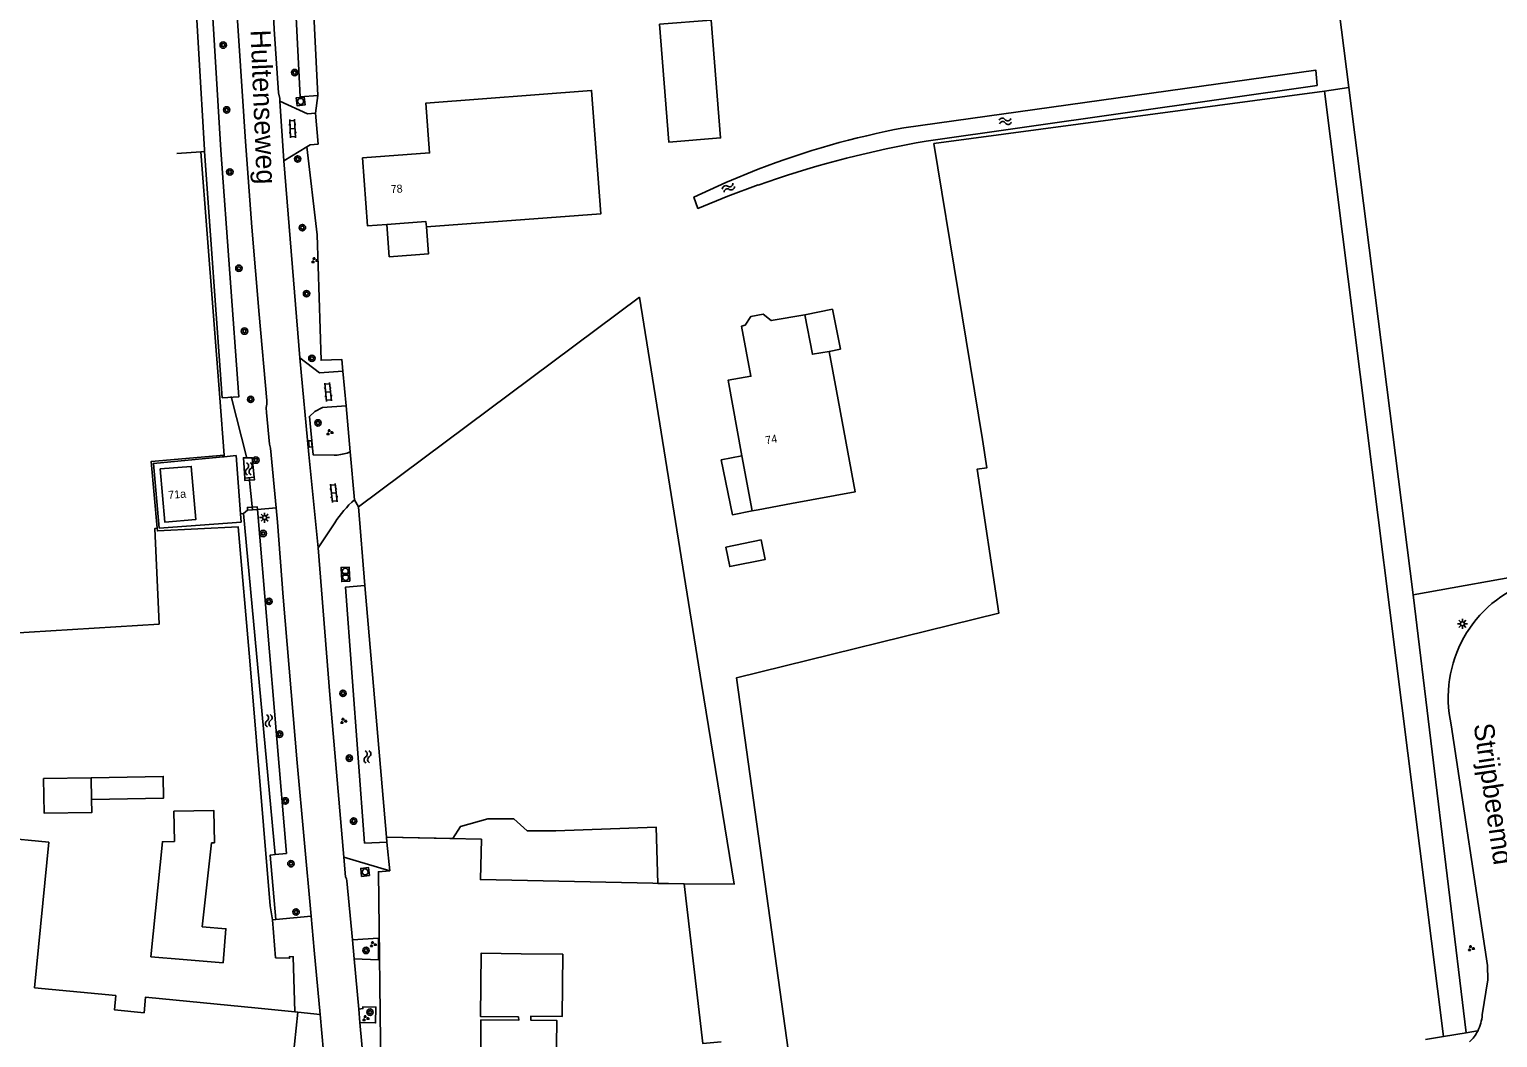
# Model space of a CAD drawing. Extents: x 124000 to 129000, y 395500 to 397503.
# Drawn here: x 125908.9 to 126092.4, y 397257.8 to 397383.8 of the extents above; entities that cross this region are included whole.
import ezdxf

# ---------------------------------------------------------------- set-up
doc = ezdxf.new("R2010")
doc.units = 0
for name, color, linetype in [('gg-afsc-draadraster', 7, 'Continuous'), ('gg-afsc-hekwerk', 7, 'Continuous'), ('gg-afsc-lijn draadraster', 7, 'Continuous'), ('gg-anno-huisnummerreeks BGT', 7, 'Continuous'), ('gg-anno-openbare ruimte label', 7, 'Continuous'), ('gg-bbg-bijgebouw', 7, 'Continuous'), ('gg-bbg-gedigitaliseerde bebouwing', 7, 'Continuous'), ('gg-bbg-gedigitaliseerde bijgebouw', 7, 'Continuous'), ('gg-bbg-hoofdgebouw', 7, 'Continuous'), ('gg-bbg-luifel en loopbrug', 7, 'Continuous'), ('gg-knt-bronhoudergrens', 7, 'Continuous'), ('gg-knt-verharding', 7, 'Continuous'), ('gg-kntw-bovenkant insteek waterloop', 7, 'Continuous'), ('gg-kwrk-duiker nz buis', 7, 'Continuous'), ('gg-kwrk-uitstroombak niveau min 01', 7, 'Continuous'), ('gt-grn-groengrens', 7, 'Continuous'), ('gt-grn-weggrens', 7, 'Continuous'), ('gt-symb-boom', 7, 'Continuous'), ('gt-symb-groenvak', 7, 'Continuous'), ('gt-symb-klinker verharding', 7, 'Continuous'), ('gt-symb-kolk', 7, 'Continuous'), ('gt-symb-lichtmast', 7, 'Continuous'), ('gt-symb-rioolschacht', 7, 'Continuous'), ('gt-symb-watersymbool', 7, 'Continuous'), ('gx-grn-maaiveld', 7, 'Continuous')]:
    doc.layers.add(name, color=color, linetype=linetype)

# ---------------------------------------------------------------- blocks, each defined once
blk = doc.blocks.new('gt0-BOOM')
at = {"layer": 'gt-symb-boom'}
for radius in [0.4, 0.2]:
    blk.add_circle((0, 0), radius, dxfattribs=at)
blk = doc.blocks.new('gt0-LMAST')
at = {"layer": 'gt-symb-lichtmast'}
for p, q in [((-0.18, 0.17), (-0.45, 0.44)), ((-0.01, 0.25), (-0.01, 0.62)), ((0.17, 0.17), (0.44, 0.44)), ((-0.26, 0), (-0.63, 0)), ((-0.18, -0.18), (-0.45, -0.45)), ((-0.01, -0.25), (-0.01, -0.63)), ((0.44, -0.45), (0.17, -0.18)), ((0.24, 0), (0.62, 0))]:
    blk.add_line(p, q, dxfattribs=at)
blk.add_circle((-0.01, 0), 0.25, dxfattribs=at)
blk = doc.blocks.new('gt0-GRVAK')
at = {"layer": 'gt-symb-groenvak'}
for p, q in [((-0.11, 0.19), (-0.23, 0.24)), ((-0.18, 0.15), (0.09, 0.15)), ((-0.09, 0.21), (-0.16, 0.32)), ((-0.05, 0.21), (-0.05, 0.39)), ((0, 0.21), (0.06, 0.32)), ((0.01, 0.19), (0.13, 0.24)), ((0.26, -0.05), (0.2, 0.06)), ((0.3, -0.05), (0.3, 0.13)), ((0.35, -0.05), (0.41, 0.06)), ((-0.25, -0.23), (-0.36, -0.18)), ((-0.32, -0.26), (-0.05, -0.26)), ((-0.23, -0.21), (-0.29, -0.09)), ((-0.18, -0.2), (-0.18, -0.02)), ((-0.14, -0.21), (-0.07, -0.09)), ((-0.12, -0.23), (0, -0.18)), ((0.24, -0.07), (0.12, -0.02)), ((0.17, -0.11), (0.44, -0.11)), ((0.37, -0.07), (0.49, -0.02))]:
    blk.add_line(p, q, dxfattribs=at)
blk = doc.blocks.new('gt0-WA')
at = {"layer": 'gt-symb-watersymbool'}
for centre, start, end in [((-0.32, 0.02), 28.0725, 151.9275), ((0.43, 0.42), 208.0725, 331.9275), ((-0.32, -0.43), 28.0725, 151.9275), ((0.43, -0.03), 208.0725, 331.9275)]:
    blk.add_arc(centre, 0.425, start, end, dxfattribs=at)
blk = doc.blocks.new('gt0-RS')
at = {"layer": 'gt-symb-rioolschacht'}
blk.add_lwpolyline([(-0.5, -0.5), (0.5, -0.5), (0.5, 0.5), (-0.5, 0.5)], close=True, dxfattribs=at)
blk.add_circle((0, 0), 0.375, dxfattribs=at)
blk = doc.blocks.new('gt0-KL1')
at = {"layer": 'gt-symb-klinker verharding'}
for p, q in [((-1.15, 0.3), (1.15, 0.3)), ((-1, -0.3), (-1, 0.3)), ((-0.5, 0.3), (-0.5, 0.45)), ((0, -0.3), (0, 0.3)), ((0.5, 0.3), (0.5, 0.45)), ((1, -0.3), (1, 0.3)), ((-1.15, -0.3), (1.15, -0.3)), ((-0.5, -0.45), (-0.5, -0.3)), ((0.5, -0.45), (0.5, -0.3))]:
    blk.add_line(p, q, dxfattribs=at)
blk = doc.blocks.new('gt0-KOLK')
at = {"layer": 'gt-symb-kolk'}
blk.add_lwpolyline([(0, 0), (0.38, 0), (0.38, 0.4), (-0.38, 0.4), (-0.38, 0), (0, 0)], dxfattribs=at)

msp = doc.modelspace()

# ---------------------------------------------------------------- linework, layer by layer
at = {"layer": 'gg-afsc-draadraster'}
for p, q in [((125985.18, 397350.34), (125950.04, 397324.15)), ((125950.04, 397324.15), (125950.86, 397314.34))]:
    msp.add_line(p, q, dxfattribs=at)
msp.add_lwpolyline([(125924.91, 397321.48), (125924.63, 397321.46), (125925.14, 397309.52), (125900.76, 397308.02)], dxfattribs=at)
at = {"layer": 'gg-afsc-hekwerk'}
for p, q in [((125927.38, 397368.31), (125930.37, 397368.54)), ((125930.37, 397368.54), (125932.72, 397337.77)), ((125932.72, 397337.77), (125933.27, 397330.6)), ((125933.02, 397330.39), (125932.7, 397330.36)), ((125933.29, 397330.42), (125933.02, 397330.39)), ((125934.77, 397330.56), (125933.29, 397330.42)), ((125935.32, 397323.3), (125934.77, 397330.56)), ((125925.16, 397321.49), (125935.4, 397322.26)), ((125935.4, 397322.26), (125935.32, 397323.3)), ((125953.96, 397278.68), (125953.6, 397282.27)), ((125953.96, 397278.68), (125953.6, 397282.27))]:
    msp.add_line(p, q, dxfattribs=at)
for points in [[(125933.27, 397330.6), (125924.16, 397329.84), (125924.91, 397321.48)], [(125932.7, 397330.36), (125924.44, 397329.58), (125925.16, 397321.49)], [(125924.91, 397321.48), (125924.94, 397321.15), (125935.02, 397321.67), (125936.49, 397304.91), (125939.03, 397274.29), (125939.3, 397272.55)], [(125953.96, 397278.68), (125952.55, 397278.56), (125952.87, 397253.92)], [(125953.96, 397278.68), (125952.55, 397278.56), (125952.87, 397253.92)], [(125939.3, 397272.55), (125939.71, 397267.82), (125941.46, 397267.75), (125941.44, 397267.96), (125941.9, 397267.95), (125942.09, 397261.06)]]:
    msp.add_lwpolyline(points, dxfattribs=at)
at = {"layer": 'gg-afsc-lijn draadraster'}
for p, q in [((125985.18, 397350.34), (125950.04, 397324.15)), ((125950.04, 397324.15), (125950.86, 397314.34))]:
    msp.add_line(p, q, dxfattribs=at)
msp.add_lwpolyline([(125995.36, 397257.33), (125993.07, 397257.12), (125990.73, 397277.04), (125965.3, 397277.59), (125965.41, 397282.63), (125953.55, 397282.88)], dxfattribs=at)
at = {"layer": 'gg-bbg-bijgebouw'}
for points in [[(125987.67, 397384.48), (125994.14, 397384.99), (125995.3, 397370.25), (125988.82, 397369.74), (125987.67, 397384.48)], [(125926.99, 397286.12), (125927.06, 397282.35), (125925.57, 397282.32), (125924.13, 397267.94), (125928.16, 397267.61)], [(125926.99, 397286.12), (125931.99, 397286.21), (125932.06, 397282.19), (125931.7, 397282.16), (125930.54, 397271.7), (125933.49, 397271.45), (125933.14, 397267.2), (125928.16, 397267.61)], [(125970.37, 397268.33), (125965.37, 397268.38), (125965.29, 397260.49), (125970.07, 397260.44)], [(125974.76, 397253.7), (125974.83, 397260), (125971.59, 397260.03), (125971.59, 397260.51), (125975.49, 397260.47), (125975.57, 397268.27), (125970.37, 397268.33)], [(125965.36, 397260.05), (125965.33, 397254.73), (125965.47, 397253.72), (125968.56, 397253.72)], [(125965.36, 397260.05), (125970.11, 397260.03), (125970.07, 397260.44)]]:
    msp.add_lwpolyline(points, dxfattribs=at)
at = {"layer": 'gg-bbg-gedigitaliseerde bebouwing'}
for p, q in [((125905.32, 397282.85), (125911.38, 397282.26)), ((125942.49, 397261.02), (125942.09, 397261.06))]:
    msp.add_line(p, q, dxfattribs=at)
msp.add_lwpolyline([(125942.09, 397261.06), (125937.52, 397261.54), (125923.47, 397262.91), (125923.28, 397260.96), (125919.56, 397261.33), (125919.73, 397263.09), (125909.6, 397264.08), (125911.38, 397282.26)], dxfattribs=at)
at = {"layer": 'gg-bbg-gedigitaliseerde bijgebouw'}
for p, q in [((125916.66, 397290.3), (125910.71, 397290.2)), ((125916.71, 397287.6), (125916.66, 397290.3))]:
    msp.add_line(p, q, dxfattribs=at)
for points in [[(125995.95, 397319.14), (126000.36, 397320.03), (126000.85, 397317.58), (125996.44, 397316.69), (125995.95, 397319.14)], [(125910.71, 397290.2), (125910.79, 397285.87), (125916.73, 397285.97), (125916.71, 397287.6)]]:
    msp.add_lwpolyline(points, dxfattribs=at)
at = {"layer": 'gg-bbg-hoofdgebouw'}
for p, q in [((126008.88, 397343.59), (126009.79, 397338.65)), ((125999.23, 397323.66), (125997.96, 397330.55)), ((126000, 397323.8), (125999.23, 397323.66)), ((126000, 397323.8), (126004.14, 397324.56))]:
    msp.add_line(p, q, dxfattribs=at)
for points in [[(125958.55, 397359.16), (125980.33, 397360.77), (125979.19, 397376.2), (125958.49, 397374.62), (125958.95, 397368.38), (125950.57, 397367.76), (125951.19, 397359.26), (125953.61, 397359.44)], [(125953.61, 397359.44), (125958.48, 397359.8), (125958.55, 397359.16)], [(125997.93, 397346.74), (125998.36, 397346.86), (125999.07, 397347.94), (126000.62, 397348.23), (126001.62, 397347.44), (126005.83, 397348.17)], [(126005.83, 397348.17), (126006.77, 397343.23), (126008.88, 397343.59)], [(125997.96, 397330.55), (125996.24, 397339.97), (125999.08, 397340.47), (125997.93, 397346.74)], [(126004.14, 397324.56), (126012.1, 397326.02), (126009.79, 397338.65)], [(125925.3, 397328.9), (125929.17, 397329.22), (125929.73, 397322.58), (125925.86, 397322.26), (125925.3, 397328.9)], [(125942.49, 397261.02), (125940.4, 397241.03), (125921.46, 397242.88), (125921.65, 397244.8), (125917.87, 397245.15), (125917.68, 397243.24), (125901.38, 397244.83)]]:
    msp.add_lwpolyline(points, dxfattribs=at)
at = {"layer": 'gg-bbg-luifel en loopbrug'}
for points in [[(125953.61, 397359.44), (125953.9, 397355.4), (125958.8, 397355.76), (125958.55, 397359.16)], [(126005.83, 397348.17), (126009.26, 397348.86), (126010.27, 397343.87), (126008.88, 397343.59)], [(125999.23, 397323.66), (125996.77, 397323.17), (125995.39, 397330.03), (125997.96, 397330.55)], [(125916.66, 397290.3), (125925.66, 397290.47), (125925.71, 397287.78), (125916.71, 397287.6)]]:
    msp.add_lwpolyline(points, dxfattribs=at)
at = {"layer": 'gg-knt-bronhoudergrens'}
for q in [(126021.93, 397369.54), (126085.6, 397257.98)]:
    msp.add_line((126070.75, 397376.1), q, dxfattribs=at)
msp.add_lwpolyline([(126005.25, 397245.54), (125997.27, 397302.78), (126030.04, 397310.86), (126027.35, 397328.86), (126028.56, 397329.04), (126028.03, 397332.58), (126021.93, 397369.54)], dxfattribs=at)
at = {"layer": 'gg-knt-verharding'}
for p, q in [((125940.23, 397374.86), (125940.75, 397367.39)), ((125943.62, 397369.16), (125940.75, 397367.39)), ((125940.75, 397367.39), (125942.74, 397342.79)), ((125942.74, 397342.79), (125945.18, 397340.91)), ((125948.1, 397341.11), (125945.18, 397340.91)), ((125945.04, 397319.04), (125947.11, 397322.17)), ((126086.58, 397296.91), (126091.11, 397266.87)), ((125948.23, 397280.39), (125953.96, 397278.68)), ((125948.61, 397277.42), (125949.3, 397270.08)), ((125939.74, 397272.6), (125939.3, 397272.55)), ((125944.14, 397273), (125939.74, 397272.6)), ((125944.53, 397268.78), (125944.14, 397273)), ((125945.27, 397260.74), (125944.53, 397268.78)), ((125949.3, 397270.08), (125949.5, 397267.67)), ((125949.5, 397267.67), (125950.09, 397261.4)), ((125950.22, 397259.72), (125950.09, 397261.4)), ((125947.09, 397240.97), (125945.27, 397260.74)), ((125950.22, 397259.72), (125950.75, 397253.87))]:
    msp.add_line(p, q, dxfattribs=at)
for points in [[(125934.05, 397500), (125935.1, 397482.48), (125936.64, 397447.42), (125937.06, 397435.53), (125937.22, 397434.95), (125937.55, 397427.43), (125937.4, 397426.79), (125939.51, 397383.86), (125940.08, 397375.88), (125940.22, 397375.19), (125940.23, 397374.86)], [(125938.61, 397337.45), (125937.66, 397348.2), (125936.74, 397359.1), (125935.95, 397369.8), (125934.68, 397388.71), (125933.66, 397409.18), (125933.24, 397416.57), (125930.95, 397471.05), (125930.49, 397479.24)], [(125940.23, 397374.86), (125943.68, 397373.28), (125944.68, 397373.36)], [(125945.01, 397369.48), (125944.01, 397369.4), (125943.62, 397369.16)], [(125942.74, 397342.79), (125943.84, 397330.7), (125945.04, 397319.04)], [(125939.76, 397324.02), (125939.06, 397331.49), (125938.95, 397331.99), (125938.56, 397335.94), (125938.54, 397336.55)], [(125944.62, 397336.09), (125945.58, 397336.58), (125948.5, 397336.8)], [(125947.41, 397330.63), (125947.03, 397330.6), (125944.38, 397330.68), (125943.93, 397335.47), (125944.62, 397336.09)], [(125944.14, 397273), (125942.39, 397292.17), (125940.65, 397312.89), (125939.93, 397322.23), (125939.76, 397324.02)], [(125945.04, 397319.04), (125946.49, 397300.67), (125948.23, 397280.39)], [(125948.23, 397280.39), (125948.44, 397277.94), (125948.58, 397277.69), (125948.61, 397277.42)], [(125949.5, 397267.67), (125952.54, 397267.56), (125952.54, 397270.29), (125949.3, 397270.08)], [(126091.11, 397266.87), (126091.15, 397265.07), (126090.45, 397260.69)], [(125950.09, 397261.4), (125950.62, 397261.47), (125950.6, 397261.68), (125952.24, 397261.66), (125952.2, 397259.68), (125950.22, 397259.72)]]:
    msp.add_lwpolyline(points, dxfattribs=at)
for centre, radius, start, end in [((125936.25, 397337.17), 2.37, 344.9511, 6.7412), ((125946.71, 397336.94), 6.35, 276.3543, 291.3494), ((125958.77, 397314.72), 13.84, 131.7347, 147.4438), ((126101.53, 397300.33), 15.33, 108.6415, 192.8607), ((126085.33, 397261.03), 5.13, 332.6066, 356.2518), ((126085.33, 397261.03), 5.13, 313.5569, 332.6494)]:
    msp.add_arc(centre, radius, start, end, dxfattribs=at)
at = {"layer": 'gg-kntw-bovenkant insteek waterloop'}
for p, q in [((125933.03, 397337.79), (125930.82, 397368.58)), ((125936.19, 397323.76), (125935.68, 397323.33)), ((125941.08, 397280.85), (125937.44, 397323.82)), ((125935.68, 397323.33), (125939.67, 397280.72)), ((125950.86, 397314.34), (125953.55, 397282.88)), ((125950.83, 397282.14), (125953.6, 397282.27)), ((125953.55, 397282.88), (125953.6, 397282.27)), ((125941.08, 397280.85), (125939.67, 397280.72))]:
    msp.add_line(p, q, dxfattribs=at)
for points in [[(125925.69, 397469.83), (125927.59, 397469.89), (125929.96, 397416.94), (125932.85, 397368.71), (125935.13, 397337.92), (125933.03, 397337.79)], [(125944.98, 397375.57), (125942.77, 397375.39), (125940.86, 397413.44), (125940.35, 397423.38), (125940.23, 397430.27), (125942.44, 397430.31)], [(125944.98, 397375.57), (125943.09, 397413.47), (125942.56, 397423.42), (125942.44, 397430.31)], [(125930.82, 397368.58), (125930.81, 397368.75), (125927.98, 397416.8), (125927.62, 397425.21)], [(126018.19, 397371.51), (126069.68, 397378.72), (126069.82, 397376.82), (126020.99, 397369.87), (126019.75, 397369.64)], [(126000, 397364.38), (125996.21, 397362.97), (125992.47, 397361.44), (125991.97, 397362.87), (125995.95, 397364.69), (126000, 397366.35)], [(125937.04, 397327.85), (125936.78, 397330.3), (125935.69, 397330.3), (125935.85, 397327.75)], [(125950.86, 397314.34), (125948.42, 397314.11), (125950.83, 397282.14)]]:
    msp.add_lwpolyline(points, dxfattribs=at)
for centre, radius, start, end in [((126037.36, 397269.36), 103.94, 100.6248, 111.0637), ((126043.07, 397242.59), 129.17, 100.4015, 109.4768)]:
    msp.add_arc(centre, radius, start, end, dxfattribs=at)
at = {"layer": 'gg-kwrk-duiker nz buis'}
for p, q in [((125936.11, 397330.23), (125934.14, 397337.96)), ((125936.8, 397323.8), (125936.42, 397327.88))]:
    msp.add_line(p, q, dxfattribs=at)
at = {"layer": 'gg-kwrk-uitstroombak niveau min 01'}
for p, q in [((125935.85, 397327.75), (125937.04, 397327.85)), ((125937.44, 397323.82), (125936.19, 397323.76))]:
    msp.add_line(p, q, dxfattribs=at)
for points in [[(125937.04, 397327.85), (125937.07, 397327.54), (125935.87, 397327.44), (125935.85, 397327.75)], [(125936.19, 397323.76), (125936.18, 397324.08), (125937.42, 397324.15), (125937.44, 397323.82)]]:
    msp.add_lwpolyline(points, dxfattribs=at)
at = {"layer": 'gt-grn-groengrens'}
for p, q in [((125944.98, 397375.57), (125944.68, 397373.36)), ((125930.37, 397368.54), (125930.82, 397368.58)), ((125948.5, 397336.8), (125949.02, 397331.02)), ((125933.27, 397330.6), (125933.29, 397330.42)), ((125937.44, 397323.82), (125939.76, 397324.02)), ((125949.56, 397325.05), (125950.04, 397324.15)), ((125935.32, 397323.3), (125935.68, 397323.33)), ((126081.82, 397313.18), (126088.45, 397258.44)), ((126083.35, 397257.62), (126085.6, 397257.98)), ((126085.6, 397257.98), (126088.45, 397258.44)), ((126088.45, 397258.44), (126089.88, 397258.67))]:
    msp.add_line(p, q, dxfattribs=at)
for points in [[(125943.62, 397369.16), (125944.88, 397358.15), (125945.39, 397342.48), (125947.97, 397342.58), (125948.1, 397341.11)], [(125939.67, 397280.72), (125939.03, 397280.66), (125939.74, 397272.6)]]:
    msp.add_lwpolyline(points, dxfattribs=at)
at = {"layer": 'gt-grn-weggrens'}
for p, q in [((125944.68, 397373.36), (125945.01, 397369.48)), ((125948.1, 397341.11), (125948.5, 397336.8)), ((125949.02, 397331.02), (125949.56, 397325.05)), ((125942.49, 397261.02), (125945.27, 397260.74))]:
    msp.add_line(p, q, dxfattribs=at)
at = {"layer": 'gx-grn-maaiveld'}
for q in [(126070.75, 397376.1), (126081.82, 397313.18)]:
    msp.add_line((126073.77, 397376.54), q, dxfattribs=at)
for points in [[(126073.77, 397376.54), (126070.69, 397400.82), (126063.71, 397453.01)], [(125953.55, 397282.88), (125961.83, 397282.71), (125962.8, 397284.21), (125966.22, 397285.16), (125969.47, 397285.16), (125971.14, 397283.66), (125974.71, 397283.66), (125987.25, 397284.13), (125987.46, 397277.11), (125990.73, 397277.04), (125997.01, 397277.02), (125992.91, 397302.08), (125985.18, 397350.34)], [(126081.82, 397313.18), (126097.62, 397315.98), (126110.36, 397318.31), (126110.37, 397318.31), (126140.89, 397323.06), (126162.59, 397326.55), (126175.29, 397329.1), (126182.54, 397330.84), (126193.44, 397334.18), (126199.37, 397337.03), (126203.72, 397339.79)]]:
    msp.add_lwpolyline(points, dxfattribs=at)

# ---------------------------------------------------------------- block references
at = {"layer": 'gt-symb-boom'}
for p in [(125933.16, 397381.86), (125942.09, 397378.42), (125933.59, 397373.76), (125942.46, 397367.63), (125933.99, 397366), (125943.05, 397359.04), (125935.12, 397353.97), (125943.57, 397350.8), (125935.82, 397346.12), (125944.24, 397342.72), (125936.59, 397337.59), (125945, 397334.65), (125937.23, 397330), (125938.15, 397320.83), (125938.88, 397312.35), (125948.12, 397300.86), (125940.21, 397295.76), (125948.91, 397292.76), (125940.92, 397287.42), (125949.45, 397284.9), (125941.62, 397279.57), (125942.26, 397273.54), (125951, 397268.74), (125951.5, 397261.02)]:
    msp.add_blockref('gt0-BOOM', p, dxfattribs=at)
at = {"layer": 'gt-symb-groenvak'}
for p in [(125944.56, 397354.97), (125946.44, 397333.47), (125948.17, 397297.4), (125951.86, 397269.49), (126089.04, 397269), (125950.94, 397260.26)]:
    msp.add_blockref('gt0-GRVAK', p, dxfattribs=at)
at = {"layer": 'gt-symb-klinker verharding'}
for p, rotation in [((125941.82, 397371.42), 92.9224726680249), ((125946.26, 397338.51), -83.96999119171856), ((125946.97, 397325.89), -83.97600691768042)]:
    msp.add_blockref('gt0-KL1', p, dxfattribs=dict(at, rotation=rotation))
at = {"layer": 'gt-symb-kolk', "rotation": 95.33444003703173}
msp.add_blockref('gt0-KOLK', (125944.25, 397332.05), dxfattribs=at)
at = {"layer": 'gt-symb-lichtmast'}
for p in [(125938.33, 397322.81), (126087.98, 397309.55)]:
    msp.add_blockref('gt0-LMAST', p, dxfattribs=at)
at = {"layer": 'gt-symb-rioolschacht'}
for p, rotation in [((125942.83, 397374.82), -174.26090150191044), ((125948.41, 397316.11), 91.89196541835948), ((125948.45, 397315.35), 92.75083479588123), ((125950.89, 397278.54), 96.94741065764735)]:
    msp.add_blockref('gt0-RS', p, dxfattribs=dict(at, rotation=rotation))
at = {"layer": 'gt-symb-watersymbool'}
for p, rotation in [((126030.8, 397372.34), 7.992313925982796), ((125996.33, 397364.05), -151.5129928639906), ((125936.36, 397328.97), -86.33074590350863), ((125938.85, 397297.5), -86.3307459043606), ((125951.18, 397292.98), -86.3307459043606)]:
    msp.add_blockref('gt0-WA', p, dxfattribs=dict(at, rotation=rotation))

# ---------------------------------------------------------------- texts
at = {"layer": 'gg-anno-huisnummerreeks BGT'}
for s, rotation, p in [('78', 4.2, (125954.12, 397363.34)), ('74', 10.4, (126000.98, 397331.96)), ('71a', 4.8, (125926.33, 397325.14))]:
    msp.add_text(s, height=1, rotation=rotation, dxfattribs=at).set_placement(p)
at = {"layer": 'gg-anno-openbare ruimte label'}
for s, rotation, p in [('Hultenseweg', 272.3, (125936.57, 397383.73)), ('Strijpbeemd', 278.2, (126089.37, 397296.95))]:
    msp.add_text(s, height=2.5, rotation=rotation, dxfattribs=at).set_placement(p)

doc.saveas('drawing.dxf')
